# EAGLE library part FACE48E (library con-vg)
CONNECTOR female, 48 pins, single, type C, rows ABC, grid 5.08 mm
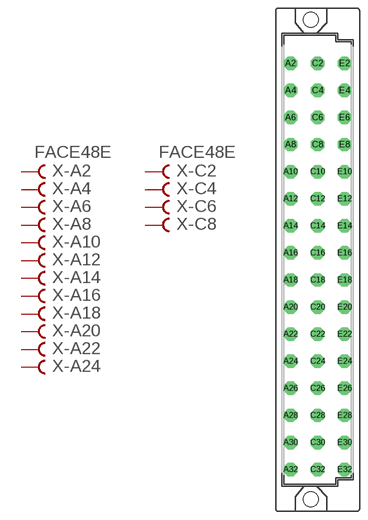
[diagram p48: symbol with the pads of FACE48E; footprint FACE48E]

Designator prefix X; gates -A2=FVAL -A4=FEM -A6=FEM -A8=FEM -A10=FEM -A12=FEM -A14=FEM -A16=FEM -A18=FEM -A20=FEM -A22=FEM -A24=FEM -C2=FVAL -C4=FEM -C6=FEM -C8=FEM -C10=FEM -C12=FEM -C14=FEM -C16=FEM -C18=FEM -C20=FEM -C22=FEM -C24=FEM -E2=FVAL -E4=FEM -E6=FEM -E8=FEM -E10=FEM -E12=FEM -E14=FEM -E16=FEM -E18=FEM -E20=FEM -E22=FEM -E24=FEM -A26=FEM -A28=FEM -A30=FEM -A32=FEM -C26=FEM -C28=FEM -C30=FEM -C32=FEM -E26=FEM -E28=FEM -E30=FEM -E32=FEM

## FACE48E  [FACE48E]
A2  -A2:B  pas
A4  -A4:B  pas
A6  -A6:B  pas
A8  -A8:B  pas
A10  -A10:B  pas
A12  -A12:B  pas
A14  -A14:B  pas
A16  -A16:B  pas
A18  -A18:B  pas
A20  -A20:B  pas
A22  -A22:B  pas
A24  -A24:B  pas
A26  -A26:B  pas
A28  -A28:B  pas
A30  -A30:B  pas
A32  -A32:B  pas
C2  -C2:B  pas
C4  -C4:B  pas
C6  -C6:B  pas
C8  -C8:B  pas
C10  -C10:B  pas
C12  -C12:B  pas
C14  -C14:B  pas
C16  -C16:B  pas
C18  -C18:B  pas
C20  -C20:B  pas
C22  -C22:B  pas
C24  -C24:B  pas
C26  -C26:B  pas
C28  -C28:B  pas
C30  -C30:B  pas
C32  -C32:B  pas
E2  -E2:B  pas
E4  -E4:B  pas
E6  -E6:B  pas
E8  -E8:B  pas
E10  -E10:B  pas
E12  -E12:B  pas
E14  -E14:B  pas
E16  -E16:B  pas
E18  -E18:B  pas
E20  -E20:B  pas
E22  -E22:B  pas
E24  -E24:B  pas
E26  -E26:B  pas
E28  -E28:B  pas
E30  -E30:B  pas
E32  -E32:B  pas

## Footprint FACE48E (pad centres in mm)
CONNECTOR female, pins 48 type E, rows ACE, grid 5.08 mm
drill 1.676 octagon: A2 -5.08,36.83; A4 -5.08,31.75; A6 -5.08,26.67; A8 -5.08,21.59; A10 -5.08,16.51; A12 -5.08,11.43; A14 -5.08,6.35; A16 -5.08,1.27; A18 -5.08,-3.81; A20 -5.08,-8.89; A22 -5.08,-13.97; A24 -5.08,-19.05; A26 -5.08,-24.13; A28 -5.08,-29.21; A30 -5.08,-34.29; A32 -5.08,-39.37; C2 0,36.83; C4 0,31.75; C6 0,26.67; C8 0,21.59; C10 0,16.51; C12 0,11.43; C14 0,6.35; C16 0,1.27; C18 0,-3.81; C20 0,-8.89; C22 0,-13.97; C24 0,-19.05; C26 0,-24.13; C28 0,-29.21; C30 0,-34.29; C32 0,-39.37; E2 5.08,36.83; E4 5.08,31.75; E6 5.08,26.67; E8 5.08,21.59; E10 5.08,16.51; E12 5.08,11.43; E14 5.08,6.35; E16 5.08,1.27; E18 5.08,-3.81; E20 5.08,-8.89; E22 5.08,-13.97; E24 5.08,-19.05; E26 5.08,-24.13; E28 5.08,-29.21; E30 5.08,-34.29; E32 5.08,-39.37
hole 2.794 at -1.27,-44.983
hole 2.794 at -1.27,44.983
